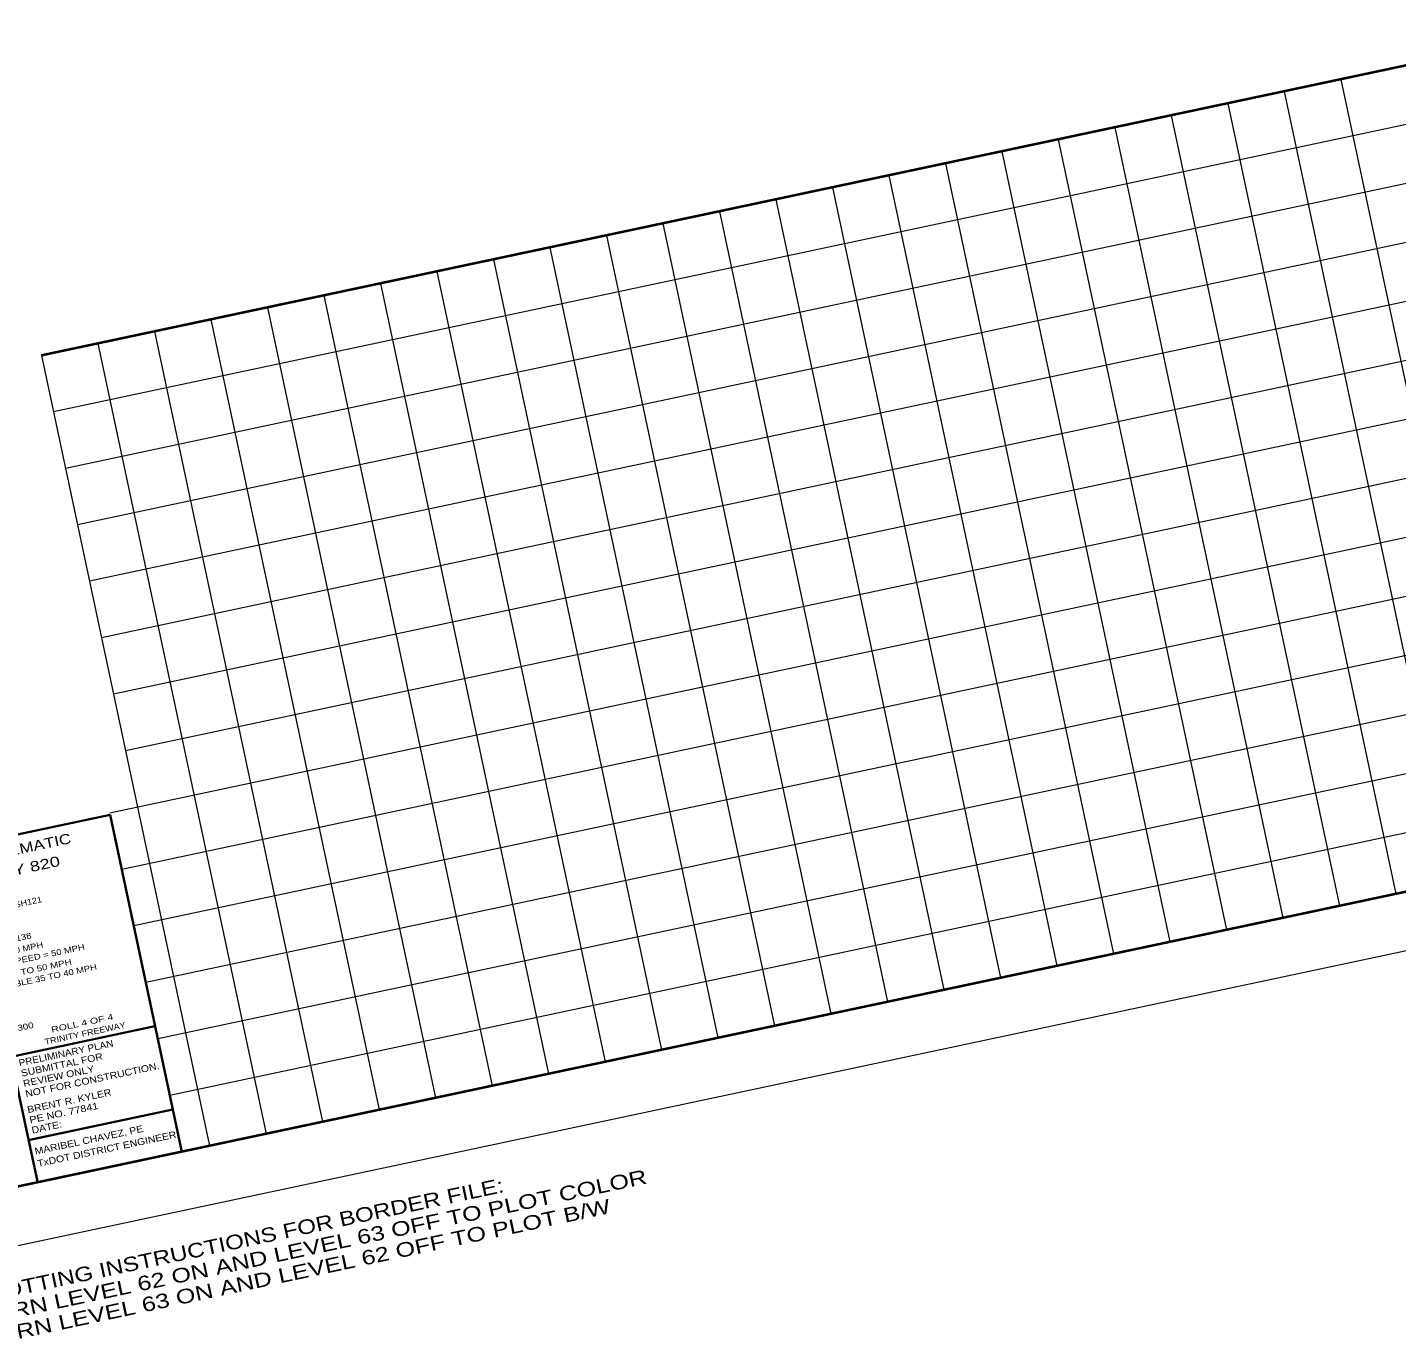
# Model space of a CAD drawing. Extents: x 2357218 to 2371708, y 6973728 to 6980157.
# Drawn here: x 2358486 to 2360857, y 6973728 to 6976010 of the extents above; entities that cross this region are included whole.
import ezdxf
from ezdxf.enums import TextEntityAlignment as Align

# ---------------------------------------------------------------- set-up
doc = ezdxf.new("R2010")
doc.units = 0
doc.header["$LTSCALE"] = 2
doc.layers.add('61', color=7, linetype='Continuous')
doc.layers.add('62', color=7, linetype='Continuous', lineweight=13)
doc.layers.add('63', color=7, linetype='Continuous', lineweight=13)

msp = doc.modelspace()

# ---------------------------------------------------------------- linework, layer by layer
at = {"layer": '62'}
for p, q in [((2370352.599, 6977447.506), (2358614.298, 6974952.455)), ((2370373.391, 6977349.687), (2358635.09, 6974854.636)), ((2370394.183, 6977251.87), (2358655.883, 6974756.815)), ((2370462.917, 6977164.241), (2358628.734, 6974648.808)), ((2370483.709, 6977066.421), (2358649.527, 6974550.988)), ((2370504.501, 6976968.6), (2358670.319, 6974453.169)), ((2370525.293, 6976870.783), (2358691.111, 6974355.349)), ((2370546.085, 6976772.963), (2358711.903, 6974257.531)), ((2370566.878, 6976675.145), (2358732.695, 6974159.712)), ((2371343.073, 6976635.653), (2358039.664, 6973807.926)), ((2360760.18, 6975919.768), (2361051.268, 6974550.299)), ((2360662.36, 6975898.976), (2360953.449, 6974529.508)), ((2360564.54, 6975878.182), (2360855.63, 6974508.716)), ((2361486.497, 6975869.675), (2358551.922, 6975245.911)), ((2360466.72, 6975857.391), (2360757.809, 6974487.923)), ((2360368.902, 6975836.599), (2360659.991, 6974467.132)), ((2360271.083, 6975815.806), (2360562.172, 6974446.34)), ((2360173.263, 6975795.015), (2360464.353, 6974425.547)), ((2361507.289, 6975771.856), (2358572.714, 6975148.093)), ((2359977.624, 6975753.432), (2360268.714, 6974383.964)), ((2360075.444, 6975774.223), (2360366.533, 6974404.756)), ((2359879.807, 6975732.639), (2360170.896, 6974363.171)), ((2359781.985, 6975711.847), (2360073.075, 6974342.38)), ((2359684.167, 6975691.056), (2359975.257, 6974321.588)), ((2361528.081, 6975674.037), (2358593.506, 6975050.273)), ((2359586.346, 6975670.263), (2359877.436, 6974300.795)), ((2359488.53, 6975649.47), (2359779.619, 6974280.002)), ((2359390.71, 6975628.679), (2359681.799, 6974259.209)), ((2359195.071, 6975587.094), (2359486.16, 6974217.626)), ((2359292.89, 6975607.887), (2359583.98, 6974238.418)), ((2359097.253, 6975566.303), (2359388.342, 6974196.833)), ((2358999.433, 6975545.511), (2359290.522, 6974176.042)), ((2358901.613, 6975524.719), (2359192.703, 6974155.25)), ((2358803.795, 6975503.927), (2359094.883, 6974134.457)), ((2358705.976, 6975483.134), (2358997.067, 6974113.666)), ((2358608.156, 6975462.343), (2358899.246, 6974092.874))]:
    msp.add_line(p, q, dxfattribs=at)
at = {"layer": '62', "lineweight": 40}
msp.add_line((2371224.464, 6976712.679), (2358116.692, 6973926.537), dxfattribs=at)
at = {"layer": '62', "lineweight": 35}
for p, q in [((2357992.598, 6974510.353), (2358629.393, 6974645.709)), ((2358629.393, 6974645.709), (2358753.487, 6974061.893)), ((2358706.979, 6974279.557), (2358070.155, 6974144.195)), ((2358503.307, 6974010.333), (2358457.357, 6974226.499)), ((2358737.656, 6974135.236), (2358488.035, 6974082.178))]:
    msp.add_line(p, q, dxfattribs=at)
at = {"layer": '63', "lineweight": 40}
for p, q in [((2370248.639, 6977936.603), (2358510.337, 6975441.549)), ((2371224.464, 6976712.679), (2358116.692, 6973926.537))]:
    msp.add_line(p, q, dxfattribs=at)
at = {"layer": '63'}
for p, q in [((2370352.599, 6977447.506), (2358614.298, 6974952.455)), ((2370373.391, 6977349.687), (2358635.09, 6974854.636)), ((2370394.183, 6977251.87), (2358655.883, 6974756.815)), ((2370462.917, 6977164.241), (2358628.734, 6974648.808)), ((2370483.709, 6977066.421), (2358649.527, 6974550.988)), ((2370504.501, 6976968.6), (2358670.319, 6974453.169)), ((2370525.293, 6976870.783), (2358691.111, 6974355.349)), ((2370546.085, 6976772.963), (2358711.903, 6974257.531)), ((2370566.878, 6976675.145), (2358732.695, 6974159.712)), ((2371343.073, 6976635.653), (2358039.664, 6973807.926)), ((2361465.705, 6975967.494), (2358531.129, 6975343.731)), ((2360760.18, 6975919.768), (2361051.268, 6974550.299)), ((2360662.36, 6975898.976), (2360953.449, 6974529.508)), ((2360564.54, 6975878.182), (2360855.63, 6974508.716)), ((2361486.497, 6975869.675), (2358551.922, 6975245.911)), ((2360466.72, 6975857.391), (2360757.809, 6974487.923)), ((2360368.902, 6975836.599), (2360659.991, 6974467.132)), ((2360271.083, 6975815.806), (2360562.172, 6974446.34)), ((2360173.263, 6975795.015), (2360464.353, 6974425.547)), ((2361507.289, 6975771.856), (2358572.714, 6975148.093)), ((2359977.624, 6975753.432), (2360268.714, 6974383.964)), ((2360075.444, 6975774.223), (2360366.533, 6974404.756)), ((2359879.807, 6975732.639), (2360170.896, 6974363.171)), ((2359781.985, 6975711.847), (2360073.075, 6974342.38)), ((2359684.167, 6975691.056), (2359975.257, 6974321.588)), ((2361528.081, 6975674.037), (2358593.506, 6975050.273)), ((2359586.346, 6975670.263), (2359877.436, 6974300.795)), ((2359488.53, 6975649.47), (2359779.619, 6974280.002)), ((2359390.71, 6975628.679), (2359681.799, 6974259.209)), ((2359195.071, 6975587.094), (2359486.16, 6974217.626)), ((2359292.89, 6975607.887), (2359583.98, 6974238.418)), ((2359097.253, 6975566.303), (2359388.342, 6974196.833)), ((2358999.433, 6975545.511), (2359290.522, 6974176.042)), ((2358901.613, 6975524.719), (2359192.703, 6974155.25)), ((2358803.795, 6975503.927), (2359094.883, 6974134.457)), ((2358705.976, 6975483.134), (2358997.067, 6974113.666)), ((2358608.156, 6975462.343), (2358899.246, 6974092.874)), ((2358510.337, 6975441.55), (2358801.428, 6974072.082)), ((2358510.337, 6975441.55), (2358801.428, 6974072.082))]:
    msp.add_line(p, q, dxfattribs=at)
at = {"layer": '63', "lineweight": 35}
for p, q in [((2357992.598, 6974510.353), (2358629.393, 6974645.709)), ((2358629.393, 6974645.709), (2358753.487, 6974061.893)), ((2358737.656, 6974135.236), (2358487.614, 6974082.088))]:
    msp.add_line(p, q, dxfattribs=at)

# ---------------------------------------------------------------- texts
at = {"layer": '61', "width": 1.15}
msp.add_text('LIMITS: IH820 NORTH INTERCHANGE AT SH121', height=10.2, rotation=12, dxfattribs=at).set_placement((2358337.676, 6974457.599), align=Align.CENTER)
at = {"layer": '62'}
for s, height, width, p in [('PRELIMINARY DESIGN SCHEMATIC', 17.5, 1.25, (2358075.107, 6974493.187)), ('INTERSTATE HIGHWAY 820', 17.5, 1.35, (2358135.192, 6974470.647)), ('CONTROL NO.  0008-13-123, 124, 138', 10.2, 1.2, (2358211.832, 6974372.018)), ('PRELIMINARY PLAN', 11.74, 1.1, (2358472.418, 6974209.845)), ('SUBMITTAL FOR', 11.74, 1.15, (2358476.212, 6974192.001)), ('REVIEW ONLY', 11.74, 1.15, (2358480.005, 6974174.157)), ('NOT FOR CONSTRUCTION.', 11.74, 1.15, (2358483.798, 6974156.313)), ('BRENT R. KYLER', 11.74, 1.15, (2358487.121, 6974128.941)), ('PE NO. 77841', 11.74, 1.2, (2358490.912, 6974111.102)), ('DATE: ', 11.74, 1.15, (2358494.705, 6974093.265)), ('MARIBEL CHAVEZ, PE', 11.74, 1.15, (2358500.059, 6974056.891)), ('TxDOT DISTRICT ENGINEER', 11.74, 1.15, (2358504.58, 6974035.626)), ('TURN LEVEL 62 ON AND LEVEL 63 OFF TO PLOT COLOR', 25, 1.3, (2358405.231, 6973761.729)), ('PLOTTING INSTRUCTIONS FOR BORDER FILE:', 25, 1.25, (2358397.538, 6973797.922)), ('TURN LEVEL 63 ON AND LEVEL 62 OFF TO PLOT B/W', 25, 1.3, (2358412.922, 6973725.536))]:
    msp.add_text(s, height=height, rotation=12, dxfattribs=dict(at, width=width)).set_placement(p)
for s, width, p in [('MAIN LANES DESIGN SPEED = 60 MPH', 1.2, (2358365.357, 6974384.543)), ('DIRECT CONNECTOR & RAMP DESIGN SPEED = 50 MPH', 1.2, (2358369.219, 6974366.37)), ('FRONTAGE ROAD DESIGN SPEED VARIABLE 35 TO 40 MPH', 1.2, (2358378.055, 6974329.019)), ('RAMP DESIGN SPEED VARIABLE 40 TO 50 MPH', 1.25, (2358373.497, 6974346.243)), ('300', 1.25, (2358483.754, 6974273.951)), ('TRINITY FREEWAY', 1.15, (2358586.98, 6974262.167)), ('ROLL 4 OF 4', 1.35, (2358581.964, 6974279.765))]:
    msp.add_text(s, height=10.2, rotation=12, dxfattribs=dict(at, width=width)).set_placement(p, align=Align.CENTER)
at = {"layer": '63'}
for s, width, p in [('MAIN LANES DESIGN SPEED = 60 MPH', 1.2, (2358365.357, 6974384.543)), ('DIRECT CONNECTOR & RAMP DESIGN SPEED = 50 MPH', 1.2, (2358369.219, 6974366.37)), ('300', 1.25, (2358483.754, 6974273.951))]:
    msp.add_text(s, height=10.2, rotation=12, dxfattribs=dict(at, width=width)).set_placement(p, align=Align.CENTER)

doc.saveas('drawing.dxf')
